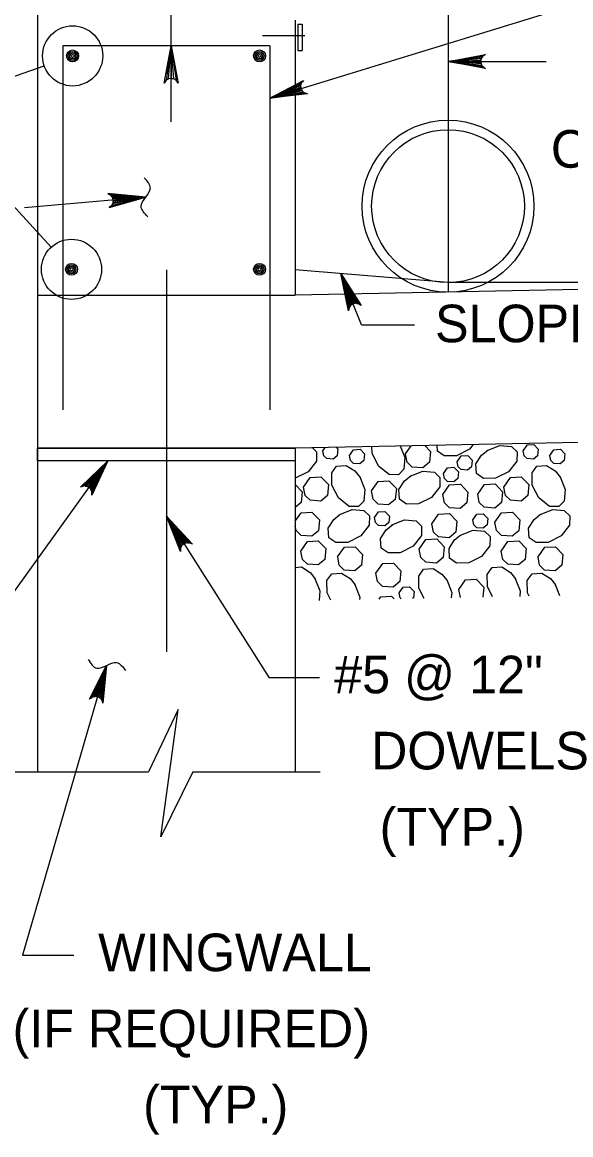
# Model space of a CAD drawing. Extents: x 636530 to 644067, y 294168 to 299122.
# Drawn here: x 638282.8 to 638326.6, y 294558.3 to 294647.1 of the extents above; entities that cross this region are included whole.
import ezdxf

# ---------------------------------------------------------------- set-up
doc = ezdxf.new("R2010")
doc.units = 0
doc.layers.add('1', color=7, linetype='Continuous')

msp = doc.modelspace()

# ---------------------------------------------------------------- linework, layer by layer
at = {"layer": '1'}
for p, q in [((638284.048, 294666.02), (638284.048, 294587.27)), ((638316.814, 294661.633), (638316.814, 294625.533)), ((638294.717, 294639.116), (638294.717, 294654.436)), ((638302.589, 294641.019), (638344.439, 294653.862)), ((638304.622, 294647.22), (638304.622, 294625.289)), ((638304.838, 294646.906), (638304.838, 294644.816)), ((638304.838, 294646.906), (638305.16, 294646.906)), ((638305.16, 294646.906), (638305.16, 294644.816)), ((638305.393, 294645.97), (638302.019, 294645.97)), ((638286.08, 294645.188), (638286.08, 294616.142)), ((638302.589, 294645.188), (638286.08, 294645.188)), ((638302.589, 294645.188), (638302.589, 294616.142)), ((638286.852, 294644.377), (638286.852, 294644.377)), ((638304.838, 294644.816), (638305.16, 294644.816)), ((638274.919, 294640.2), (638284.587, 294643.584)), ((638316.814, 294643.94), (638324.654, 294643.94)), ((638274.919, 294640.2), (638285.138, 294629.118)), ((638792.302, 294635.042), (638304.622, 294625.289)), ((638292.689, 294633.104), (638283.014, 294632.251)), ((638286.764, 294627.353), (638286.764, 294627.353)), ((638294.335, 294627.319), (638294.335, 294596.839)), ((638316.814, 294626.295), (638304.622, 294627.31)), ((638309.915, 294622.921), (638308.249, 294627.008)), ((638354.914, 294626.295), (638316.814, 294626.295)), ((638284.048, 294625.289), (638304.622, 294625.289)), ((638792.302, 294622.848), (638304.622, 294613.094)), ((638309.915, 294622.921), (638314.127, 294622.921)), ((638304.622, 294613.094), (638284.048, 294613.094)), ((638304.622, 294613.094), (638304.622, 294587.27)), ((638289.673, 294612.079), (638268.264, 294582.34)), ((638304.622, 294612.079), (638284.048, 294612.079)), ((638294.335, 294607.654), (638302.53, 294594.769)), ((638289.569, 294595.76), (638282.85, 294572.654)), ((638306.545, 294594.769), (638302.53, 294594.769)), ((638281.664, 294587.27), (638292.916, 294587.27)), ((638296.435, 294587.27), (638306.617, 294587.27)), ((638282.85, 294572.654), (638286.96, 294572.654))]:
    msp.add_line(p, q, dxfattribs=at)
for points in [[(638294.717, 294645.188), (638295.277, 294642.205), (638295.117, 294642.435), (638294.917, 294642.553), (638294.717, 294642.588), (638294.517, 294642.553), (638294.317, 294642.435), (638294.158, 294642.205), (638294.717, 294645.188), (638294.317, 294642.435), (638294.517, 294642.553), (638294.717, 294645.188), (638294.717, 294642.588), (638294.917, 294642.553), (638294.717, 294645.188), (638295.117, 294642.435)], [(638316.814, 294643.94), (638319.796, 294644.499), (638319.681, 294644.419), (638319.566, 294644.34), (638319.507, 294644.24), (638319.448, 294644.14), (638319.431, 294644.04), (638319.414, 294643.94), (638319.431, 294643.84), (638319.448, 294643.74), (638319.507, 294643.64), (638319.566, 294643.54), (638319.681, 294643.46), (638319.796, 294643.38), (638316.814, 294643.94), (638319.681, 294643.46), (638319.566, 294643.54), (638316.814, 294643.94), (638319.507, 294643.64), (638319.448, 294643.74), (638316.814, 294643.94), (638319.431, 294643.84), (638319.414, 294643.94), (638316.814, 294643.94), (638319.431, 294644.04), (638319.448, 294644.14), (638316.814, 294643.94), (638319.507, 294644.24), (638319.566, 294644.34), (638316.814, 294643.94), (638319.681, 294644.419)], [(638302.589, 294641.019), (638305.276, 294642.428), (638305.19, 294642.319), (638305.103, 294642.209), (638305.076, 294642.096), (638305.049, 294641.983), (638305.062, 294641.882), (638305.075, 294641.782), (638305.12, 294641.691), (638305.166, 294641.6), (638305.252, 294641.522), (638305.338, 294641.444), (638305.471, 294641.402), (638305.605, 294641.359), (638302.589, 294641.019), (638305.471, 294641.402), (638305.338, 294641.444), (638302.589, 294641.019), (638305.252, 294641.522), (638305.166, 294641.6), (638302.589, 294641.019), (638305.12, 294641.691), (638305.075, 294641.782), (638302.589, 294641.019), (638305.062, 294641.882), (638305.049, 294641.983), (638302.589, 294641.019), (638305.076, 294642.096), (638305.103, 294642.209), (638302.589, 294641.019), (638305.19, 294642.319)], [(638292.689, 294633.104), (638289.669, 294633.399), (638289.79, 294633.33), (638289.912, 294633.261), (638289.98, 294633.166), (638290.047, 294633.072), (638290.073, 294632.974), (638290.099, 294632.875), (638290.091, 294632.774), (638290.082, 294632.673), (638290.032, 294632.568), (638289.982, 294632.464), (638289.874, 294632.374), (638289.767, 294632.285), (638292.689, 294633.104), (638289.874, 294632.374), (638289.982, 294632.464), (638292.689, 294633.104), (638290.032, 294632.568), (638290.082, 294632.673), (638292.689, 294633.104), (638290.091, 294632.774), (638290.099, 294632.875), (638292.689, 294633.104), (638290.073, 294632.974), (638290.047, 294633.072), (638292.689, 294633.104), (638289.98, 294633.166), (638289.912, 294633.261), (638292.689, 294633.104), (638289.79, 294633.33)], [(638308.249, 294627.008), (638309.893, 294624.457), (638309.776, 294624.533), (638309.658, 294624.61), (638309.544, 294624.627), (638309.429, 294624.644), (638309.329, 294624.622), (638309.23, 294624.6), (638309.144, 294624.547), (638309.058, 294624.493), (638308.988, 294624.4), (638308.918, 294624.308), (638308.887, 294624.171), (638308.857, 294624.035), (638308.249, 294627.008), (638308.887, 294624.171), (638308.918, 294624.308), (638308.249, 294627.008), (638308.988, 294624.4), (638309.058, 294624.493), (638308.249, 294627.008), (638309.144, 294624.547), (638309.23, 294624.6), (638308.249, 294627.008), (638309.329, 294624.622), (638309.429, 294624.644), (638308.249, 294627.008), (638309.544, 294624.627), (638309.658, 294624.61), (638308.249, 294627.008), (638309.776, 294624.533)], [(638305.992, 294613.122), (638306.328, 294612.803), (638306.314, 294612.053), (638305.647, 294611.2), (638304.622, 294610.688)], [(638306.831, 294612.885), (638307.012, 294613.142)], [(638307.876, 294613.159), (638308.027, 294613.003), (638307.976, 294612.482), (638307.657, 294612.217), (638307.149, 294612.255), (638306.909, 294612.487), (638306.832, 294612.885)], [(638312.997, 294613.262), (638313.366, 294612.333), (638313.286, 294611.408), (638312.869, 294610.969), (638312.119, 294610.983), (638311.266, 294611.65), (638310.751, 294612.68), (638310.742, 294613.217)], [(638313.424, 294612.631), (638313.88, 294613.28)], [(638314.959, 294613.301), (638315.418, 294612.826), (638315.331, 294611.959), (638314.801, 294611.517), (638313.953, 294611.579), (638313.554, 294611.965), (638313.425, 294612.631)], [(638318.814, 294613.378), (638318.516, 294612.998), (638317.486, 294612.483), (638316.515, 294612.465), (638315.968, 294612.854), (638315.937, 294613.321)], [(638319.949, 294612.901), (638320.955, 294613.3), (638321.879, 294613.22), (638322.319, 294612.803), (638322.305, 294612.053), (638321.638, 294611.2), (638320.607, 294610.685), (638319.637, 294610.668), (638319.09, 294611.057), (638319.038, 294611.83), (638319.481, 294612.522), (638319.989, 294612.927)], [(638322.822, 294612.885), (638323.145, 294613.345), (638323.66, 294613.374), (638324.018, 294613.003), (638323.967, 294612.482), (638323.648, 294612.217), (638323.139, 294612.255), (638322.9, 294612.487), (638322.823, 294612.885)], [(638308.95, 294612.507), (638309.273, 294612.966), (638309.788, 294612.996), (638310.146, 294612.624), (638310.094, 294612.104), (638309.776, 294611.839), (638309.267, 294611.876), (638309.028, 294612.108), (638308.95, 294612.507)], [(638317.551, 294612.003), (638317.874, 294612.462), (638318.389, 294612.491), (638318.747, 294612.12), (638318.696, 294611.6), (638318.377, 294611.335), (638317.869, 294611.372), (638317.629, 294611.604), (638317.552, 294612.003)], [(638324.941, 294612.507), (638325.263, 294612.966), (638325.779, 294612.996), (638326.137, 294612.624), (638326.085, 294612.104), (638325.767, 294611.839), (638325.258, 294611.876), (638325.019, 294612.108), (638324.941, 294612.507)], [(638289.673, 294612.079), (638288.385, 294609.331), (638288.387, 294609.471), (638288.39, 294609.611), (638288.343, 294609.717), (638288.297, 294609.824), (638288.226, 294609.896), (638288.154, 294609.969), (638288.063, 294610.013), (638287.972, 294610.058), (638287.856, 294610.068), (638287.741, 294610.078), (638287.609, 294610.032), (638287.477, 294609.985), (638289.673, 294612.079), (638287.609, 294610.032), (638287.741, 294610.078), (638289.673, 294612.079), (638287.856, 294610.068), (638287.972, 294610.058), (638289.673, 294612.079), (638288.063, 294610.013), (638288.154, 294609.969), (638289.673, 294612.079), (638288.226, 294609.896), (638288.297, 294609.824), (638289.673, 294612.079), (638288.343, 294609.717), (638288.39, 294609.611), (638289.673, 294612.079), (638288.387, 294609.471)], [(638309.763, 294610.801), (638310.162, 294609.795), (638310.082, 294608.87), (638309.664, 294608.431), (638308.914, 294608.445), (638308.062, 294609.112), (638307.547, 294610.142), (638307.53, 294611.113), (638307.918, 294611.66), (638308.692, 294611.711), (638309.383, 294611.268), (638309.789, 294610.76)], [(638316.442, 294611.07), (638316.765, 294611.529), (638317.28, 294611.558), (638317.638, 294611.187), (638317.586, 294610.667), (638317.268, 294610.402), (638316.759, 294610.439), (638316.52, 294610.671), (638316.442, 294611.07)], [(638325.753, 294610.801), (638326.153, 294609.795), (638326.073, 294608.87), (638325.655, 294608.431), (638324.905, 294608.445), (638324.053, 294609.112), (638323.538, 294610.142), (638323.521, 294611.113), (638323.909, 294611.66), (638324.683, 294611.711), (638325.374, 294611.268), (638325.779, 294610.76)], [(638305.276, 294609.981), (638305.813, 294610.746), (638306.672, 294610.795), (638307.269, 294610.176), (638307.183, 294609.309), (638306.652, 294608.868), (638305.805, 294608.929), (638305.406, 294609.316), (638305.276, 294609.981)], [(638310.699, 294609.672), (638311.237, 294610.437), (638312.095, 294610.486), (638312.692, 294609.867), (638312.606, 294609), (638312.075, 294608.559), (638311.227, 294608.62), (638310.829, 294609.007), (638310.699, 294609.672)], [(638313.8, 294610.852), (638314.807, 294611.251), (638315.731, 294611.171), (638316.17, 294610.753), (638316.156, 294610.003), (638315.489, 294609.151), (638314.459, 294608.636), (638313.488, 294608.619), (638312.941, 294609.007), (638312.889, 294609.781), (638313.333, 294610.472), (638313.841, 294610.877)], [(638321.267, 294609.981), (638321.804, 294610.746), (638322.663, 294610.795), (638323.26, 294610.176), (638323.174, 294609.309), (638322.643, 294608.868), (638321.795, 294608.929), (638321.397, 294609.316), (638321.267, 294609.981)], [(638304.622, 294610.198), (638305.183, 294609.615), (638305.097, 294608.748), (638304.622, 294608.352)], [(638316.406, 294609.389), (638316.944, 294610.153), (638317.803, 294610.203), (638318.399, 294609.584), (638318.313, 294608.716), (638317.783, 294608.275), (638316.935, 294608.337), (638316.536, 294608.723), (638316.407, 294609.388)], [(638319.181, 294609.42), (638319.719, 294610.185), (638320.577, 294610.234), (638321.174, 294609.615), (638321.088, 294608.748), (638320.557, 294608.307), (638319.709, 294608.368), (638319.311, 294608.755), (638319.181, 294609.42)], [(638304.622, 294607.261), (638305.097, 294607.937), (638305.955, 294607.986), (638306.552, 294607.367), (638306.466, 294606.5), (638305.935, 294606.059), (638305.088, 294606.12), (638304.689, 294606.507), (638304.622, 294606.852)], [(638308.168, 294607.784), (638309.174, 294608.183), (638310.098, 294608.103), (638310.537, 294607.685), (638310.524, 294606.935), (638309.857, 294606.083), (638308.827, 294605.568), (638307.855, 294605.551), (638307.309, 294605.939), (638307.257, 294606.713), (638307.701, 294607.405), (638308.209, 294607.81)], [(638310.944, 294607.547), (638311.267, 294608.006), (638311.782, 294608.035), (638312.14, 294607.664), (638312.088, 294607.144), (638311.77, 294606.879), (638311.261, 294606.916), (638311.022, 294607.148), (638310.944, 294607.547)], [(638315.524, 294607.056), (638316.062, 294607.821), (638316.92, 294607.87), (638317.517, 294607.251), (638317.431, 294606.384), (638316.901, 294605.943), (638316.053, 294606.004), (638315.654, 294606.391), (638315.524, 294607.056)], [(638318.787, 294607.371), (638319.11, 294607.829), (638319.625, 294607.859), (638319.983, 294607.487), (638319.931, 294606.967), (638319.613, 294606.703), (638319.104, 294606.739), (638318.865, 294606.971), (638318.787, 294607.37)], [(638320.55, 294607.172), (638321.087, 294607.937), (638321.946, 294607.986), (638322.543, 294607.367), (638322.457, 294606.5), (638321.926, 294606.059), (638321.079, 294606.12), (638320.679, 294606.507), (638320.55, 294607.172)], [(638324.159, 294607.784), (638325.165, 294608.183), (638326.089, 294608.103), (638326.528, 294607.685), (638326.515, 294606.935), (638325.848, 294606.083), (638324.817, 294605.568), (638323.846, 294605.551), (638323.3, 294605.939), (638323.248, 294606.713), (638323.691, 294607.405), (638324.199, 294607.81)], [(638294.335, 294607.654), (638296.407, 294605.437), (638296.278, 294605.492), (638296.149, 294605.546), (638296.033, 294605.542), (638295.917, 294605.538), (638295.824, 294605.499), (638295.73, 294605.46), (638295.655, 294605.392), (638295.58, 294605.324), (638295.527, 294605.22), (638295.474, 294605.116), (638295.469, 294604.977), (638295.463, 294604.837), (638294.335, 294607.654), (638295.469, 294604.977), (638295.474, 294605.116), (638294.335, 294607.654), (638295.527, 294605.22), (638295.58, 294605.324), (638294.335, 294607.654), (638295.655, 294605.392), (638295.73, 294605.46), (638294.335, 294607.654), (638295.824, 294605.499), (638295.917, 294605.538), (638294.335, 294607.654), (638296.033, 294605.542), (638296.149, 294605.546), (638294.335, 294607.654), (638296.278, 294605.492)], [(638312.337, 294606.958), (638313.343, 294607.357), (638314.268, 294607.277), (638314.707, 294606.859), (638314.693, 294606.109), (638314.026, 294605.257), (638312.996, 294604.742), (638312.025, 294604.725), (638311.479, 294605.113), (638311.427, 294605.887), (638311.87, 294606.579), (638312.378, 294606.984)], [(638317.803, 294606.145), (638318.809, 294606.543), (638319.734, 294606.463), (638320.173, 294606.046), (638320.159, 294605.296), (638319.492, 294604.444), (638318.462, 294603.929), (638317.491, 294603.911), (638316.944, 294604.3), (638316.893, 294605.073), (638317.336, 294605.765), (638317.844, 294606.17)], [(638305.065, 294604.882), (638305.603, 294605.647), (638306.461, 294605.696), (638307.058, 294605.077), (638306.972, 294604.21), (638306.441, 294603.769), (638305.594, 294603.83), (638305.195, 294604.217), (638305.065, 294604.882)], [(638308.005, 294604.413), (638308.543, 294605.178), (638309.402, 294605.227), (638309.999, 294604.609), (638309.912, 294603.741), (638309.382, 294603.3), (638308.534, 294603.361), (638308.135, 294603.748), (638308.006, 294604.413)], [(638314.512, 294605.032), (638315.05, 294605.797), (638315.908, 294605.846), (638316.505, 294605.227), (638316.419, 294604.36), (638315.889, 294603.919), (638315.041, 294603.98), (638314.642, 294604.367), (638314.512, 294605.032)], [(638321.056, 294604.882), (638321.593, 294605.647), (638322.452, 294605.696), (638323.049, 294605.077), (638322.963, 294604.21), (638322.432, 294603.769), (638321.585, 294603.83), (638321.186, 294604.217), (638321.056, 294604.882)], [(638323.996, 294604.413), (638324.534, 294605.178), (638325.393, 294605.227), (638325.989, 294604.609), (638325.903, 294603.741), (638325.373, 294603.3), (638324.525, 294603.361), (638324.126, 294603.748), (638323.997, 294604.413)], [(638304.622, 294603.58), (638305.113, 294603.613), (638305.805, 294603.17), (638306.21, 294602.662)], [(638311.063, 294603.112), (638311.601, 294603.877), (638312.459, 294603.926), (638313.057, 294603.307), (638312.97, 294602.44), (638312.44, 294601.999), (638311.592, 294602.06), (638311.193, 294602.447), (638311.063, 294603.112)], [(638314.897, 294601.105), (638314.493, 294601.913), (638314.476, 294602.885), (638314.864, 294603.431), (638315.638, 294603.483), (638316.329, 294603.039), (638316.735, 294602.531)], [(638320.373, 294601.215), (638319.959, 294602.044), (638319.942, 294603.015), (638320.33, 294603.561), (638321.104, 294603.613), (638321.795, 294603.17), (638322.201, 294602.662)], [(638306.184, 294602.702), (638306.583, 294601.696), (638306.517, 294600.938)], [(638307.456, 294600.957), (638307.157, 294601.556), (638307.14, 294602.527), (638307.528, 294603.073), (638308.301, 294603.125), (638308.993, 294602.682), (638309.399, 294602.174)], [(638316.709, 294602.572), (638317.108, 294601.566), (638317.072, 294601.149)], [(638317.675, 294601.811), (638318.213, 294602.576), (638319.071, 294602.625), (638319.669, 294602.006), (638319.588, 294601.199)], [(638322.175, 294602.702), (638322.574, 294601.696), (638322.536, 294601.258)], [(638323.289, 294601.273), (638323.148, 294601.556), (638323.131, 294602.527), (638323.519, 294603.073), (638324.292, 294603.125), (638324.984, 294602.682), (638325.389, 294602.174)], [(638309.373, 294602.214), (638309.771, 294601.208), (638309.754, 294601.003)], [(638312.911, 294601.545), (638313.234, 294602.004), (638313.749, 294602.033), (638314.107, 294601.662), (638314.055, 294601.141), (638313.99, 294601.087)], [(638313.068, 294601.069), (638312.989, 294601.146), (638312.911, 294601.545)], [(638317.802, 294601.164), (638317.675, 294601.811)], [(638325.363, 294602.214), (638325.717, 294601.322)], [(638304.628, 294600.9), (638304.622, 294600.905)], [(638311.319, 294601.034), (638311.45, 294601.221), (638312.309, 294601.27), (638312.514, 294601.058)], [(638289.569, 294595.76), (638289.274, 294592.74), (638289.229, 294592.873), (638289.185, 294593.005), (638289.105, 294593.09), (638289.026, 294593.175), (638288.935, 294593.22), (638288.843, 294593.264), (638288.743, 294593.275), (638288.642, 294593.287), (638288.529, 294593.258), (638288.417, 294593.229), (638288.308, 294593.141), (638288.2, 294593.053), (638289.569, 294595.76), (638288.308, 294593.141), (638288.417, 294593.229), (638289.569, 294595.76), (638288.529, 294593.258), (638288.642, 294593.287), (638289.569, 294595.76), (638288.743, 294593.275), (638288.843, 294593.264), (638289.569, 294595.76), (638288.935, 294593.22), (638289.026, 294593.175), (638289.569, 294595.76), (638289.105, 294593.09), (638289.185, 294593.005), (638289.569, 294595.76), (638289.229, 294592.873)], [(638296.435, 294587.27), (638293.897, 294582.084), (638295.277, 294592.233), (638292.916, 294587.27)]]:
    msp.add_lwpolyline(points, dxfattribs=at)
msp.add_lwpolyline([(638284.048, 294613.094), (638304.622, 294613.094), (638304.622, 294612.079), (638284.048, 294612.079)], close=True, dxfattribs=at)
for centre, radius in [((638286.852, 294644.377), 2.4), ((638286.852, 294644.377), 0.476), ((638286.852, 294644.377), 0.357), ((638286.852, 294644.377), 0.238), ((638286.852, 294644.377), 0.119), ((638301.77, 294644.377), 0.476), ((638301.77, 294644.377), 0.357), ((638301.77, 294644.377), 0.238), ((638301.77, 294644.377), 0.119), ((638316.814, 294632.391), 6.858), ((638316.814, 294632.391), 6.096), ((638286.764, 294627.353), 2.4), ((638286.764, 294627.353), 0.476), ((638286.764, 294627.353), 0.357), ((638286.764, 294627.353), 0.238), ((638286.764, 294627.353), 0.119), ((638301.77, 294627.353), 0.476), ((638301.77, 294627.353), 0.357), ((638301.77, 294627.353), 0.238), ((638301.77, 294627.353), 0.119)]:
    msp.add_circle(centre, radius, dxfattribs=at)
for points in [[(638292.858, 294631.553), (638292.322, 294632.373), (638293.06, 294633.842), (638292.573, 294634.654)], [(638288.081, 294596.227), (638288.781, 294595.542), (638290.366, 294595.981), (638291.068, 294595.346)]]:
    msp.add_spline(points, degree=3, dxfattribs=at)

# ---------------------------------------------------------------- texts
msp.add_text('OUTLET PIPE (ROADWAY ITEM)', height=3, rotation=360, dxfattribs=at).set_placement((638325.034, 294635.461))
for s, p in [('SLOPE BOTTOM OF TROUGH', (638315.778, 294621.534)), ('#5 @ 12"', (638307.729, 294593.532)), ('DOWELS', (638310.67, 294587.46)), ('(TYP.)', (638311.355, 294581.388)), ('WINGWALL', (638288.887, 294571.363)), ('(IF REQUIRED)', (638282.061, 294565.291)), ('(TYP.)', (638292.478, 294559.219))]:
    msp.add_text(s, height=3, dxfattribs=at).set_placement(p)

doc.saveas('drawing.dxf')
